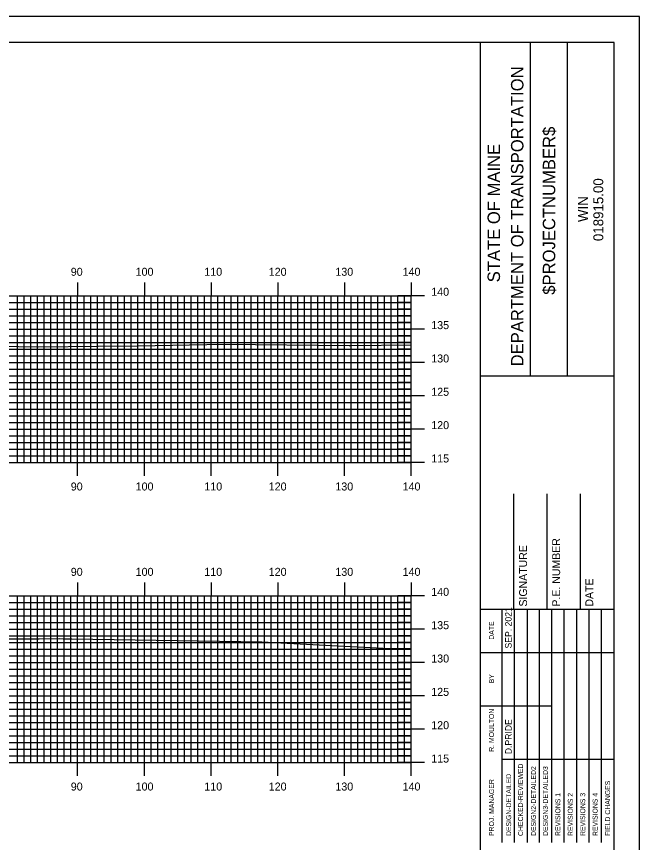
# Model space of a CAD drawing. Extents: x 841782 to 842125, y 363538 to 363758.
# Drawn here: x 842028.2 to 842121.6, y 363633.7 to 363757.6 of the extents above; entities that cross this region are included whole.
import ezdxf

# ---------------------------------------------------------------- set-up
doc = ezdxf.new("R2010")
doc.units = 0
for name, color, linetype in [('BORDER', 7, 'Continuous'), ('H_V ANNOTATION', 7, 'Continuous'), ('MAJOR', 7, 'Continuous'), ('MINOR', 7, 'Continuous'), ('PLOT BOUNDARY', 7, 'Continuous'), ('S_Roadway_Centerline', 7, 'Continuous')]:
    doc.layers.add(name, color=color, linetype=linetype)

msp = doc.modelspace()

# ---------------------------------------------------------------- linework, layer by layer
at = {"layer": 'BORDER'}
for p, q in [((842097.77, 363543.72), (842097.77, 363753.72)), ((842105.23, 363703.72), (842105.23, 363753.72)), ((842110.82, 363703.72), (842110.82, 363753.72)), ((842097.77, 363703.71), (842117.77, 363703.71)), ((842102.77, 363668.73), (842102.77, 363686.02)), ((842107.77, 363668.73), (842107.77, 363686.02)), ((842112.77, 363668.73), (842112.77, 363686.02)), ((842097.77, 363668.73), (842117.77, 363668.73))]:
    msp.add_line(p, q, dxfattribs=at)
msp.add_lwpolyline([(841797.77, 363543.72), (842117.77, 363543.72), (842117.77, 363753.72), (841797.77, 363753.72)], close=True, dxfattribs=at)
for points in [[(842101, 363662.23), (842101, 363668.73)], [(842102.87, 363633.73), (842102.87, 363668.73)], [(842104.73, 363668.73), (842104.73, 363633.73)], [(842106.59, 363633.73), (842106.59, 363668.73)], [(842108.46, 363633.73), (842108.46, 363668.73)], [(842110.32, 363633.73), (842110.32, 363668.73)], [(842112.18, 363633.73), (842112.18, 363668.73)], [(842114.05, 363633.73), (842114.05, 363668.73)], [(842115.91, 363633.73), (842115.91, 363668.73)], [(842101, 363633.73), (842101, 363667.31)], [(842097.77, 363662.23), (842117.77, 363662.23)], [(842097.77, 363654.23), (842101, 363654.23)], [(842101, 363654.23), (842108.46, 363654.23)], [(842101, 363646.23), (842117.77, 363646.23)]]:
    msp.add_lwpolyline(points, dxfattribs=at)
at = {"layer": 'MAJOR'}
for p, q in [((842037.37, 363717.73), (842037.37, 363715.72)), ((842047.37, 363717.73), (842047.37, 363715.72)), ((842057.37, 363717.73), (842057.37, 363715.72)), ((842067.37, 363717.73), (842067.37, 363715.72)), ((842077.37, 363717.73), (842077.37, 363715.72)), ((842087.37, 363717.73), (842087.37, 363715.72)), ((841807.37, 363715.72), (842087.37, 363715.72)), ((841807.37, 363715.72), (842087.37, 363715.72)), ((842037.37, 363690.72), (842037.37, 363715.72)), ((842047.37, 363690.72), (842047.37, 363715.72)), ((842057.37, 363690.72), (842057.37, 363715.72)), ((842067.37, 363690.72), (842067.37, 363715.72)), ((842077.37, 363690.72), (842077.37, 363715.72)), ((842089.38, 363715.72), (842085.37, 363715.72)), ((842087.37, 363690.72), (842087.37, 363715.72)), ((842087.37, 363690.72), (842087.37, 363715.72)), ((841807.37, 363710.72), (842087.37, 363710.72)), ((842089.38, 363710.72), (842085.37, 363710.72)), ((841807.37, 363705.72), (842087.37, 363705.72)), ((842089.38, 363705.72), (842085.37, 363705.72)), ((841807.37, 363700.72), (842087.37, 363700.72)), ((842089.38, 363700.72), (842085.37, 363700.72)), ((841807.37, 363695.72), (842087.37, 363695.72)), ((842089.38, 363695.72), (842085.37, 363695.72)), ((841807.37, 363690.72), (842087.37, 363690.72)), ((841807.37, 363690.72), (842087.37, 363690.72)), ((842037.37, 363688.72), (842037.37, 363690.72)), ((842047.37, 363688.72), (842047.37, 363690.72)), ((842057.37, 363688.72), (842057.37, 363690.72)), ((842067.37, 363688.72), (842067.37, 363690.72)), ((842077.37, 363688.72), (842077.37, 363690.72)), ((842089.38, 363690.72), (842085.37, 363690.72)), ((842087.37, 363688.72), (842087.37, 363690.72)), ((842037.37, 363672.73), (842037.37, 363670.72)), ((842047.37, 363672.73), (842047.37, 363670.72)), ((842057.37, 363672.73), (842057.37, 363670.72)), ((842067.37, 363672.73), (842067.37, 363670.72)), ((842077.37, 363672.73), (842077.37, 363670.72)), ((842087.37, 363672.73), (842087.37, 363670.72)), ((841807.37, 363670.72), (842087.37, 363670.72)), ((841807.37, 363670.72), (842087.37, 363670.72)), ((842037.37, 363645.72), (842037.37, 363670.72)), ((842047.37, 363645.72), (842047.37, 363670.72)), ((842057.37, 363645.72), (842057.37, 363670.72)), ((842067.37, 363645.72), (842067.37, 363670.72)), ((842077.37, 363645.72), (842077.37, 363670.72)), ((842089.38, 363670.72), (842085.37, 363670.72)), ((842087.37, 363645.72), (842087.37, 363670.72)), ((842087.37, 363645.72), (842087.37, 363670.72)), ((841807.37, 363665.72), (842087.37, 363665.72)), ((842089.38, 363665.72), (842085.37, 363665.72)), ((841807.37, 363660.72), (842087.37, 363660.72)), ((842089.38, 363660.72), (842085.37, 363660.72)), ((841807.37, 363655.72), (842087.37, 363655.72)), ((842089.38, 363655.72), (842085.37, 363655.72)), ((841807.37, 363650.72), (842087.37, 363650.72)), ((842089.38, 363650.72), (842085.37, 363650.72)), ((841807.37, 363645.72), (842087.37, 363645.72)), ((841807.37, 363645.72), (842087.37, 363645.72)), ((842037.37, 363643.72), (842037.37, 363645.72)), ((842047.37, 363643.72), (842047.37, 363645.72)), ((842057.37, 363643.72), (842057.37, 363645.72)), ((842067.37, 363643.72), (842067.37, 363645.72)), ((842077.37, 363643.72), (842077.37, 363645.72)), ((842089.38, 363645.72), (842085.37, 363645.72)), ((842087.37, 363643.72), (842087.37, 363645.72))]:
    msp.add_line(p, q, dxfattribs=at)
at = {"layer": 'MINOR'}
for p, q in [((842028.37, 363690.72), (842028.37, 363715.72)), ((842029.37, 363690.72), (842029.37, 363715.72)), ((842030.37, 363690.72), (842030.37, 363715.72)), ((842031.37, 363690.72), (842031.37, 363715.72)), ((842032.37, 363690.72), (842032.37, 363715.72)), ((842033.37, 363690.72), (842033.37, 363715.72)), ((842034.37, 363690.72), (842034.37, 363715.72)), ((842035.37, 363690.72), (842035.37, 363715.72)), ((842036.37, 363690.72), (842036.37, 363715.72)), ((842038.37, 363690.72), (842038.37, 363715.72)), ((842039.37, 363690.72), (842039.37, 363715.72)), ((842040.37, 363690.72), (842040.37, 363715.72)), ((842041.37, 363690.72), (842041.37, 363715.72)), ((842042.37, 363690.72), (842042.37, 363715.72)), ((842043.37, 363690.72), (842043.37, 363715.72)), ((842044.37, 363690.72), (842044.37, 363715.72)), ((842045.37, 363690.72), (842045.37, 363715.72)), ((842046.37, 363690.72), (842046.37, 363715.72)), ((842048.37, 363690.72), (842048.37, 363715.72)), ((842049.37, 363690.72), (842049.37, 363715.72)), ((842050.37, 363690.72), (842050.37, 363715.72)), ((842051.37, 363690.72), (842051.37, 363715.72)), ((842052.37, 363690.72), (842052.37, 363715.72)), ((842053.37, 363690.72), (842053.37, 363715.72)), ((842054.37, 363690.72), (842054.37, 363715.72)), ((842055.37, 363690.72), (842055.37, 363715.72)), ((842056.37, 363690.72), (842056.37, 363715.72)), ((842058.37, 363690.72), (842058.37, 363715.72)), ((842059.37, 363690.72), (842059.37, 363715.72)), ((842060.37, 363690.72), (842060.37, 363715.72)), ((842061.37, 363690.72), (842061.37, 363715.72)), ((842062.37, 363690.72), (842062.37, 363715.72)), ((842063.37, 363690.72), (842063.37, 363715.72)), ((842064.37, 363690.72), (842064.37, 363715.72)), ((842065.37, 363690.72), (842065.37, 363715.72)), ((842066.37, 363690.72), (842066.37, 363715.72)), ((842068.37, 363690.72), (842068.37, 363715.72)), ((842069.37, 363690.72), (842069.37, 363715.72)), ((842070.37, 363690.72), (842070.37, 363715.72)), ((842071.37, 363690.72), (842071.37, 363715.72)), ((842072.37, 363690.72), (842072.37, 363715.72)), ((842073.37, 363690.72), (842073.37, 363715.72)), ((842074.37, 363690.72), (842074.37, 363715.72)), ((842075.37, 363690.72), (842075.37, 363715.72)), ((842076.37, 363690.72), (842076.37, 363715.72)), ((842078.37, 363690.72), (842078.37, 363715.72)), ((842079.37, 363690.72), (842079.37, 363715.72)), ((842080.37, 363690.72), (842080.37, 363715.72)), ((842081.37, 363690.72), (842081.37, 363715.72)), ((842082.37, 363690.72), (842082.37, 363715.72)), ((842083.37, 363690.72), (842083.37, 363715.72)), ((842084.37, 363690.72), (842084.37, 363715.72)), ((842085.37, 363690.72), (842085.37, 363715.72)), ((842086.37, 363690.72), (842086.37, 363715.72)), ((841807.37, 363714.72), (842087.37, 363714.72)), ((842087.37, 363714.72), (842085.37, 363714.72)), ((841807.37, 363713.72), (842087.37, 363713.72)), ((842087.37, 363713.72), (842085.37, 363713.72)), ((841807.37, 363712.72), (842087.37, 363712.72)), ((841807.37, 363711.72), (842087.37, 363711.72)), ((842087.37, 363712.72), (842085.37, 363712.72)), ((842087.37, 363711.72), (842085.37, 363711.72)), ((841807.37, 363709.72), (842087.37, 363709.72)), ((842087.37, 363709.72), (842085.37, 363709.72)), ((841807.37, 363708.72), (842087.37, 363708.72)), ((842087.37, 363708.72), (842085.37, 363708.72)), ((841807.37, 363707.72), (842087.37, 363707.72)), ((841807.37, 363706.72), (842087.37, 363706.72)), ((842087.37, 363707.72), (842085.37, 363707.72)), ((842087.37, 363706.72), (842085.37, 363706.72)), ((841807.37, 363704.72), (842087.37, 363704.72)), ((842087.37, 363704.72), (842085.37, 363704.72)), ((841807.37, 363703.72), (842087.37, 363703.72)), ((842087.37, 363703.72), (842085.37, 363703.72)), ((841807.37, 363702.72), (842087.37, 363702.72)), ((842087.37, 363702.72), (842085.37, 363702.72)), ((841807.37, 363701.72), (842087.37, 363701.72)), ((842087.37, 363701.72), (842085.37, 363701.72)), ((841807.37, 363699.72), (842087.37, 363699.72)), ((842087.37, 363699.72), (842085.37, 363699.72)), ((841807.37, 363698.72), (842087.37, 363698.72)), ((842087.37, 363698.72), (842085.37, 363698.72)), ((841807.37, 363697.72), (842087.37, 363697.72)), ((842087.37, 363697.72), (842085.37, 363697.72)), ((841807.37, 363696.72), (842087.37, 363696.72)), ((842087.37, 363696.72), (842085.37, 363696.72)), ((841807.37, 363694.72), (842087.37, 363694.72)), ((842087.37, 363694.72), (842085.37, 363694.72)), ((841807.37, 363693.72), (842087.37, 363693.72)), ((842087.37, 363693.72), (842085.37, 363693.72)), ((841807.37, 363692.72), (842087.37, 363692.72)), ((842087.37, 363692.72), (842085.37, 363692.72)), ((841807.37, 363691.72), (842087.37, 363691.72)), ((842087.37, 363691.72), (842085.37, 363691.72)), ((841807.37, 363669.72), (842087.37, 363669.72)), ((842028.37, 363645.72), (842028.37, 363670.72)), ((842029.37, 363645.72), (842029.37, 363670.72)), ((842030.37, 363645.72), (842030.37, 363670.72)), ((842031.37, 363645.72), (842031.37, 363670.72)), ((842032.37, 363645.72), (842032.37, 363670.72)), ((842033.37, 363645.72), (842033.37, 363670.72)), ((842034.37, 363645.72), (842034.37, 363670.72)), ((842035.37, 363645.72), (842035.37, 363670.72)), ((842036.37, 363645.72), (842036.37, 363670.72)), ((842038.37, 363645.72), (842038.37, 363670.72)), ((842039.37, 363645.72), (842039.37, 363670.72)), ((842040.37, 363645.72), (842040.37, 363670.72)), ((842041.37, 363645.72), (842041.37, 363670.72)), ((842042.37, 363645.72), (842042.37, 363670.72)), ((842043.37, 363645.72), (842043.37, 363670.72)), ((842044.37, 363645.72), (842044.37, 363670.72)), ((842045.37, 363645.72), (842045.37, 363670.72)), ((842046.37, 363645.72), (842046.37, 363670.72)), ((842048.37, 363645.72), (842048.37, 363670.72)), ((842049.37, 363645.72), (842049.37, 363670.72)), ((842050.37, 363645.72), (842050.37, 363670.72)), ((842051.37, 363645.72), (842051.37, 363670.72)), ((842052.37, 363645.72), (842052.37, 363670.72)), ((842053.37, 363645.72), (842053.37, 363670.72)), ((842054.37, 363645.72), (842054.37, 363670.72)), ((842055.37, 363645.72), (842055.37, 363670.72)), ((842056.37, 363645.72), (842056.37, 363670.72)), ((842058.37, 363645.72), (842058.37, 363670.72)), ((842059.37, 363645.72), (842059.37, 363670.72)), ((842060.37, 363645.72), (842060.37, 363670.72)), ((842061.37, 363645.72), (842061.37, 363670.72)), ((842062.37, 363645.72), (842062.37, 363670.72)), ((842063.37, 363645.72), (842063.37, 363670.72)), ((842064.37, 363645.72), (842064.37, 363670.72)), ((842065.37, 363645.72), (842065.37, 363670.72)), ((842066.37, 363645.72), (842066.37, 363670.72)), ((842068.37, 363645.72), (842068.37, 363670.72)), ((842069.37, 363645.72), (842069.37, 363670.72)), ((842070.37, 363645.72), (842070.37, 363670.72)), ((842071.37, 363645.72), (842071.37, 363670.72)), ((842072.37, 363645.72), (842072.37, 363670.72)), ((842073.37, 363645.72), (842073.37, 363670.72)), ((842074.37, 363645.72), (842074.37, 363670.72)), ((842075.37, 363645.72), (842075.37, 363670.72)), ((842076.37, 363645.72), (842076.37, 363670.72)), ((842078.37, 363645.72), (842078.37, 363670.72)), ((842079.37, 363645.72), (842079.37, 363670.72)), ((842080.37, 363645.72), (842080.37, 363670.72)), ((842081.37, 363645.72), (842081.37, 363670.72)), ((842082.37, 363645.72), (842082.37, 363670.72)), ((842083.37, 363645.72), (842083.37, 363670.72)), ((842084.37, 363645.72), (842084.37, 363670.72)), ((842085.37, 363645.72), (842085.37, 363670.72)), ((842087.37, 363669.72), (842085.37, 363669.72)), ((842086.37, 363645.72), (842086.37, 363670.72)), ((841807.37, 363668.72), (842087.37, 363668.72)), ((842087.37, 363668.72), (842085.37, 363668.72)), ((841807.37, 363667.72), (842087.37, 363667.72)), ((842087.37, 363667.72), (842085.37, 363667.72)), ((841807.37, 363666.72), (842087.37, 363666.72)), ((842087.37, 363666.72), (842085.37, 363666.72)), ((841807.37, 363664.72), (842087.37, 363664.72)), ((842087.37, 363664.72), (842085.37, 363664.72)), ((841807.37, 363663.72), (842087.37, 363663.72)), ((842087.37, 363663.72), (842085.37, 363663.72)), ((841807.37, 363662.72), (842087.37, 363662.72)), ((842087.37, 363662.72), (842085.37, 363662.72)), ((841807.37, 363661.72), (842087.37, 363661.72)), ((842087.37, 363661.72), (842085.37, 363661.72)), ((841807.37, 363659.72), (842087.37, 363659.72)), ((842087.37, 363659.72), (842085.37, 363659.72)), ((841807.37, 363658.72), (842087.37, 363658.72)), ((842087.37, 363658.72), (842085.37, 363658.72)), ((841807.37, 363657.72), (842087.37, 363657.72)), ((842087.37, 363657.72), (842085.37, 363657.72)), ((841807.37, 363656.72), (842087.37, 363656.72)), ((842087.37, 363656.72), (842085.37, 363656.72)), ((841807.37, 363654.72), (842087.37, 363654.72)), ((842087.37, 363654.72), (842085.37, 363654.72)), ((841807.37, 363653.72), (842087.37, 363653.72)), ((842087.37, 363653.72), (842085.37, 363653.72)), ((841807.37, 363652.72), (842087.37, 363652.72)), ((842087.37, 363652.72), (842085.37, 363652.72)), ((841807.37, 363651.72), (842087.37, 363651.72)), ((842087.37, 363651.72), (842085.37, 363651.72)), ((841807.37, 363649.72), (842087.37, 363649.72)), ((842087.37, 363649.72), (842085.37, 363649.72)), ((841807.37, 363648.72), (842087.37, 363648.72)), ((842087.37, 363648.72), (842085.37, 363648.72)), ((841807.37, 363647.72), (842087.37, 363647.72)), ((842087.37, 363647.72), (842085.37, 363647.72)), ((841807.37, 363646.72), (842087.37, 363646.72)), ((842087.37, 363646.72), (842085.37, 363646.72))]:
    msp.add_line(p, q, dxfattribs=at)
at = {"layer": 'PLOT BOUNDARY'}
msp.add_lwpolyline([(841781.59, 363537.6), (842121.59, 363537.6), (842121.59, 363757.6), (841781.59, 363757.6)], close=True, dxfattribs=at)
at = {"layer": 'S_Roadway_Centerline'}
for points in [[(842022.46, 363708.19), (842031.49, 363708.07), (842040.44, 363708.14), (842046.38, 363708.23), (842059.34, 363708.48), (842078.08, 363708.27), (842078.21, 363708.27), (842078.27, 363708.26), (842078.4, 363708.26), (842087.37, 363708.34)], [(842018.57, 363664.29), (842031.62, 363664.29), (842034.67, 363664.3), (842035.22, 363664.29), (842036.48, 363664.26), (842064.97, 363663.82), (842083.14, 363662.89), (842087.37, 363662.82)]]:
    msp.add_lwpolyline(points, dxfattribs=at)

# ---------------------------------------------------------------- texts
at = {"layer": 'BORDER'}
for s, height, p in [('DEPARTMENT OF TRANSPORTATION', 1.8635, (842104.19, 363705.13)), ('$PROJECTNUMBER$', 1.8635, (842108.96, 363715.88)), ('STATE OF MAINE', 1.8635, (842100.68, 363717.74)), ('018915.00', 1.491, (842116.16, 363723.92)), ('WIN', 1.491, (842113.85, 363726.78)), ('SIGNATURE', 1.181, (842104.73, 363669.11)), ('P.E. NUMBER', 1.1811, (842109.69, 363669.11)), ('DATE', 1.181, (842114.65, 363669.11)), ('SEP. 2021', 0.969, (842102.42, 363662.82)), ('DATE', 0.743, (842099.78, 363664.14)), ('BY', 0.743, (842099.78, 363657.6)), ('R. MOULTON', 0.745, (842099.78, 363647.33)), ('D.PRIDE', 0.969, (842102.42, 363646.97)), ('CHECKED-REVIEWED', 0.7455, (842104.13, 363634.7)), ('DESIGN2-DETAILED2', 0.7455, (842106.07, 363634.7)), ('DESIGN3-DETAILED3', 0.7455, (842107.86, 363634.7)), ('DESIGN-DETAILED', 0.7455, (842102.35, 363634.7)), ('PROJ. MANAGER', 0.7455, (842099.78, 363634.7)), ('FIELD CHANGES', 0.7455, (842117.18, 363634.7)), ('REVISIONS 1', 0.7455, (842109.72, 363634.7)), ('REVISIONS 2', 0.7455, (842111.59, 363634.7)), ('REVISIONS 3', 0.7455, (842113.45, 363634.7)), ('REVISIONS 4', 0.7455, (842115.31, 363634.7))]:
    msp.add_text(s, height=height, rotation=90, dxfattribs=at).set_placement(p)
at = {"layer": 'H_V ANNOTATION'}
for s, p in [('90', (842036.34, 363718.72)), ('100', (842046.06, 363718.72)), ('110', (842056.36, 363718.72)), ('120', (842066.01, 363718.72)), ('130', (842076, 363718.72)), ('140', (842086.08, 363718.72)), ('140', (842090.37, 363715.72)), ('135', (842090.37, 363710.72)), ('130', (842090.37, 363705.72)), ('125', (842090.37, 363700.72)), ('120', (842090.37, 363695.72)), ('115', (842090.37, 363690.72)), ('90', (842036.34, 363686.52)), ('100', (842046.06, 363686.52)), ('110', (842056.36, 363686.52)), ('120', (842066.01, 363686.52)), ('130', (842076, 363686.52)), ('140', (842086.08, 363686.52)), ('90', (842036.34, 363673.72)), ('100', (842046.06, 363673.72)), ('110', (842056.36, 363673.72)), ('120', (842066.01, 363673.72)), ('130', (842076, 363673.72)), ('140', (842086.08, 363673.72)), ('140', (842090.37, 363670.72)), ('135', (842090.37, 363665.72)), ('130', (842090.37, 363660.72)), ('125', (842090.37, 363655.72)), ('120', (842090.37, 363650.72)), ('115', (842090.37, 363645.72)), ('90', (842036.34, 363641.52)), ('100', (842046.06, 363641.52)), ('110', (842056.36, 363641.52)), ('120', (842066.01, 363641.52)), ('130', (842076, 363641.52)), ('140', (842086.08, 363641.52))]:
    msp.add_text(s, height=1.2, dxfattribs=at).set_placement(p)

doc.saveas('drawing.dxf')
